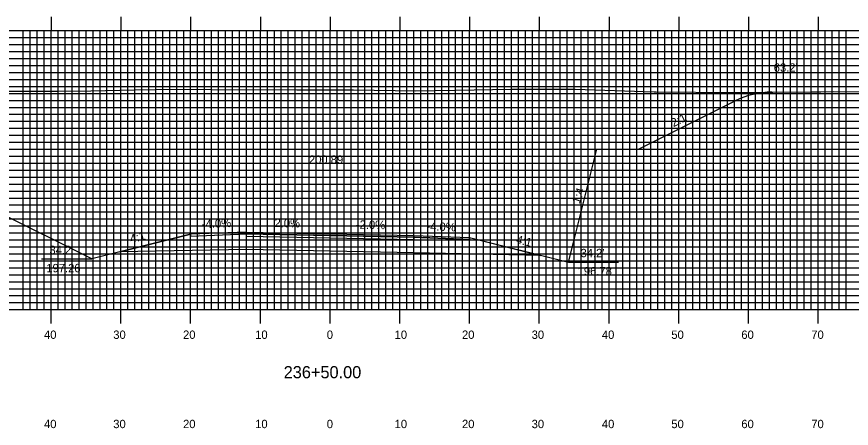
# Model space of a CAD drawing. Extents: x 1800749 to 1801092, y 442591 to 442811.
# Drawn here: x 1800869.6 to 1800989.3, y 442651.6 to 442710.7 of the extents above; entities that cross this region are included whole.
import ezdxf

# ---------------------------------------------------------------- set-up
doc = ezdxf.new("R2010")
doc.units = 0
for name, color, linetype in [('ANNOTATION', 7, 'Continuous'), ('D_Roadway_Centerline', 7, 'Continuous'), ('D_Roadway_Centerline_Text', 7, 'Continuous'), ('D_Roadway_Edge_Shoulder', 7, 'Continuous'), ('D_Roadway_Edge_TW', 7, 'Continuous'), ('D_Roadway_Pavement', 7, 'Continuous'), ('D_Roadway_SlopeLines', 7, 'Continuous'), ('D_Roadway_SubGrade', 7, 'Continuous'), ('D_Text_Standard', 7, 'Continuous'), ('H_V ANNOTATION', 7, 'Continuous'), ('MAJOR', 7, 'Continuous'), ('MINOR', 7, 'Continuous'), ('PDRAIN', 7, 'Continuous'), ('S_Roadway_Centerline', 7, 'Continuous')]:
    doc.layers.add(name, color=color, linetype=linetype)

msp = doc.modelspace()

# ---------------------------------------------------------------- linework, layer by layer
at = {"layer": 'ANNOTATION'}
for p, q in [((1800960.78, 442692.67), (1800972.63, 442698.59)), ((1800958.78, 442691.67), (1800960.78, 442692.67)), ((1800949.72, 442679.45), (1800952.78, 442691.67)), ((1800952.78, 442691.67), (1800958.78, 442691.67)), ((1800948.72, 442675.45), (1800949.72, 442679.45))]:
    msp.add_line(p, q, dxfattribs=at)
msp.add_arc((1800978, 442687.86), 12, 90.3864, 116.5651, dxfattribs=at)
at = {"layer": 'D_Roadway_Edge_Shoulder'}
for points in [[(1800902.55, 442679.79), (1800894.55, 442679.47), (1800894.55, 442679.22), (1800902.55, 442679.54)], [(1800926.55, 442679.31), (1800934.55, 442678.99), (1800934.55, 442678.74), (1800926.55, 442679.06)]]:
    msp.add_lwpolyline(points, close=True, dxfattribs=at)
at = {"layer": 'D_Roadway_Edge_TW'}
msp.add_lwpolyline([(1800902.55, 442679.54), (1800902.55, 442679.79), (1800914.55, 442679.55), (1800926.55, 442679.31), (1800926.55, 442679.06), (1800914.55, 442679.3)], close=True, dxfattribs=at)
at = {"layer": 'D_Roadway_Pavement'}
msp.add_lwpolyline([(1800902.55, 442679.13), (1800902.55, 442679.54), (1800914.55, 442679.3), (1800926.55, 442679.06), (1800926.55, 442678.65), (1800914.55, 442678.89)], close=True, dxfattribs=at)
at = {"layer": 'D_Roadway_SlopeLines'}
msp.add_line((1800880.38, 442675.93), (1800837.81, 442697.21), dxfattribs=at)
for points in [[(1800894.55, 442679.47), (1800880.38, 442675.93)], [(1800934.55, 442678.99), (1800948.72, 442675.45)]]:
    msp.add_lwpolyline(points, dxfattribs=at)
at = {"layer": 'D_Roadway_SubGrade'}
msp.add_lwpolyline([(1800902.55, 442677.29), (1800884.38, 442676.93), (1800894.55, 442679.47), (1800894.55, 442679.22), (1800902.55, 442679.54), (1800914.55, 442679.3), (1800926.55, 442679.06), (1800934.55, 442678.74), (1800934.55, 442678.99), (1800944.72, 442676.45), (1800926.55, 442676.81), (1800914.55, 442677.05)], close=True, dxfattribs=at)
at = {"layer": 'MAJOR'}
for p, q in [((1800874.55, 442710.67), (1800874.55, 442708.67)), ((1800884.55, 442710.67), (1800884.55, 442708.67)), ((1800894.55, 442710.67), (1800894.55, 442708.67)), ((1800904.55, 442710.67), (1800904.55, 442708.67)), ((1800914.55, 442710.67), (1800914.55, 442708.67)), ((1800924.55, 442710.67), (1800924.55, 442708.67)), ((1800934.55, 442710.67), (1800934.55, 442708.67)), ((1800944.55, 442710.67), (1800944.55, 442708.67)), ((1800954.55, 442710.67), (1800954.55, 442708.67)), ((1800964.55, 442710.67), (1800964.55, 442708.67)), ((1800974.55, 442710.67), (1800974.55, 442708.67)), ((1800984.55, 442710.67), (1800984.55, 442708.67)), ((1800774.55, 442708.67), (1801054.55, 442708.67)), ((1800774.55, 442708.67), (1801054.55, 442708.67)), ((1800874.55, 442668.67), (1800874.55, 442708.67)), ((1800884.55, 442668.67), (1800884.55, 442708.67)), ((1800894.55, 442668.67), (1800894.55, 442708.67)), ((1800904.55, 442668.67), (1800904.55, 442708.67)), ((1800914.55, 442668.67), (1800914.55, 442708.67)), ((1800924.55, 442668.67), (1800924.55, 442708.67)), ((1800934.55, 442668.67), (1800934.55, 442708.67)), ((1800944.55, 442668.67), (1800944.55, 442708.67)), ((1800954.55, 442668.67), (1800954.55, 442708.67)), ((1800964.55, 442668.67), (1800964.55, 442708.67)), ((1800974.55, 442668.67), (1800974.55, 442708.67)), ((1800984.55, 442668.67), (1800984.55, 442708.67)), ((1800774.55, 442703.67), (1801054.55, 442703.67)), ((1800774.55, 442698.67), (1801054.55, 442698.67)), ((1800774.55, 442693.67), (1801054.55, 442693.67)), ((1800774.55, 442688.67), (1801054.55, 442688.67)), ((1800774.55, 442683.67), (1801054.55, 442683.67)), ((1800774.55, 442678.67), (1801054.55, 442678.67)), ((1800774.55, 442673.67), (1801054.55, 442673.67)), ((1800774.55, 442668.67), (1801054.55, 442668.67)), ((1800774.55, 442668.67), (1801054.55, 442668.67)), ((1800874.55, 442666.66), (1800874.55, 442668.67)), ((1800884.55, 442666.66), (1800884.55, 442668.67)), ((1800894.55, 442666.66), (1800894.55, 442668.67)), ((1800904.55, 442666.66), (1800904.55, 442668.67)), ((1800914.55, 442666.66), (1800914.55, 442668.67)), ((1800924.55, 442666.66), (1800924.55, 442668.67)), ((1800934.55, 442666.66), (1800934.55, 442668.67)), ((1800944.55, 442666.66), (1800944.55, 442668.67)), ((1800954.55, 442666.66), (1800954.55, 442668.67)), ((1800964.55, 442666.66), (1800964.55, 442668.67)), ((1800974.55, 442666.66), (1800974.55, 442668.67)), ((1800984.55, 442666.66), (1800984.55, 442668.67))]:
    msp.add_line(p, q, dxfattribs=at)
at = {"layer": 'MINOR'}
for p, q in [((1800870.55, 442668.67), (1800870.55, 442708.67)), ((1800871.55, 442668.67), (1800871.55, 442708.67)), ((1800872.55, 442668.67), (1800872.55, 442708.67)), ((1800873.55, 442668.67), (1800873.55, 442708.67)), ((1800875.55, 442668.67), (1800875.55, 442708.67)), ((1800876.55, 442668.67), (1800876.55, 442708.67)), ((1800877.55, 442668.67), (1800877.55, 442708.67)), ((1800878.55, 442668.67), (1800878.55, 442708.67)), ((1800879.55, 442668.67), (1800879.55, 442708.67)), ((1800880.55, 442668.67), (1800880.55, 442708.67)), ((1800881.55, 442668.67), (1800881.55, 442708.67)), ((1800882.55, 442668.67), (1800882.55, 442708.67)), ((1800883.55, 442668.67), (1800883.55, 442708.67)), ((1800885.55, 442668.67), (1800885.55, 442708.67)), ((1800886.55, 442668.67), (1800886.55, 442708.67)), ((1800887.55, 442668.67), (1800887.55, 442708.67)), ((1800888.55, 442668.67), (1800888.55, 442708.67)), ((1800889.55, 442668.67), (1800889.55, 442708.67)), ((1800890.55, 442668.67), (1800890.55, 442708.67)), ((1800891.55, 442668.67), (1800891.55, 442708.67)), ((1800892.55, 442668.67), (1800892.55, 442708.67)), ((1800893.55, 442668.67), (1800893.55, 442708.67)), ((1800895.55, 442668.67), (1800895.55, 442708.67)), ((1800896.55, 442668.67), (1800896.55, 442708.67)), ((1800897.55, 442668.67), (1800897.55, 442708.67)), ((1800898.55, 442668.67), (1800898.55, 442708.67)), ((1800899.55, 442668.67), (1800899.55, 442708.67)), ((1800900.55, 442668.67), (1800900.55, 442708.67)), ((1800901.55, 442668.67), (1800901.55, 442708.67)), ((1800902.55, 442668.67), (1800902.55, 442708.67)), ((1800903.55, 442668.67), (1800903.55, 442708.67)), ((1800905.55, 442668.67), (1800905.55, 442708.67)), ((1800906.55, 442668.67), (1800906.55, 442708.67)), ((1800907.55, 442668.67), (1800907.55, 442708.67)), ((1800908.55, 442668.67), (1800908.55, 442708.67)), ((1800909.55, 442668.67), (1800909.55, 442708.67)), ((1800910.55, 442668.67), (1800910.55, 442708.67)), ((1800911.55, 442668.67), (1800911.55, 442708.67)), ((1800912.55, 442668.67), (1800912.55, 442708.67)), ((1800913.55, 442668.67), (1800913.55, 442708.67)), ((1800915.55, 442668.67), (1800915.55, 442708.67)), ((1800916.55, 442668.67), (1800916.55, 442708.67)), ((1800917.55, 442668.67), (1800917.55, 442708.67)), ((1800918.55, 442668.67), (1800918.55, 442708.67)), ((1800919.55, 442668.67), (1800919.55, 442708.67)), ((1800920.55, 442668.67), (1800920.55, 442708.67)), ((1800921.55, 442668.67), (1800921.55, 442708.67)), ((1800922.55, 442668.67), (1800922.55, 442708.67)), ((1800923.55, 442668.67), (1800923.55, 442708.67)), ((1800925.55, 442668.67), (1800925.55, 442708.67)), ((1800926.55, 442668.67), (1800926.55, 442708.67)), ((1800927.55, 442668.67), (1800927.55, 442708.67)), ((1800928.55, 442668.67), (1800928.55, 442708.67)), ((1800929.55, 442668.67), (1800929.55, 442708.67)), ((1800930.55, 442668.67), (1800930.55, 442708.67)), ((1800931.55, 442668.67), (1800931.55, 442708.67)), ((1800932.55, 442668.67), (1800932.55, 442708.67)), ((1800933.55, 442668.67), (1800933.55, 442708.67)), ((1800935.55, 442668.67), (1800935.55, 442708.67)), ((1800936.55, 442668.67), (1800936.55, 442708.67)), ((1800937.55, 442668.67), (1800937.55, 442708.67)), ((1800938.55, 442668.67), (1800938.55, 442708.67)), ((1800939.55, 442668.67), (1800939.55, 442708.67)), ((1800940.55, 442668.67), (1800940.55, 442708.67)), ((1800941.55, 442668.67), (1800941.55, 442708.67)), ((1800942.55, 442668.67), (1800942.55, 442708.67)), ((1800943.55, 442668.67), (1800943.55, 442708.67)), ((1800945.55, 442668.67), (1800945.55, 442708.67)), ((1800946.55, 442668.67), (1800946.55, 442708.67)), ((1800947.55, 442668.67), (1800947.55, 442708.67)), ((1800948.55, 442668.67), (1800948.55, 442708.67)), ((1800949.55, 442668.67), (1800949.55, 442708.67)), ((1800950.55, 442668.67), (1800950.55, 442708.67)), ((1800951.55, 442668.67), (1800951.55, 442708.67)), ((1800952.55, 442668.67), (1800952.55, 442708.67)), ((1800953.55, 442668.67), (1800953.55, 442708.67)), ((1800955.55, 442668.67), (1800955.55, 442708.67)), ((1800956.55, 442668.67), (1800956.55, 442708.67)), ((1800957.55, 442668.67), (1800957.55, 442708.67)), ((1800958.55, 442668.67), (1800958.55, 442708.67)), ((1800959.55, 442668.67), (1800959.55, 442708.67)), ((1800960.55, 442668.67), (1800960.55, 442708.67)), ((1800961.55, 442668.67), (1800961.55, 442708.67)), ((1800962.55, 442668.67), (1800962.55, 442708.67)), ((1800963.55, 442668.67), (1800963.55, 442708.67)), ((1800965.55, 442668.67), (1800965.55, 442708.67)), ((1800966.55, 442668.67), (1800966.55, 442708.67)), ((1800967.55, 442668.67), (1800967.55, 442708.67)), ((1800968.55, 442668.67), (1800968.55, 442708.67)), ((1800969.55, 442668.67), (1800969.55, 442708.67)), ((1800970.55, 442668.67), (1800970.55, 442708.67)), ((1800971.55, 442668.67), (1800971.55, 442708.67)), ((1800972.55, 442668.67), (1800972.55, 442708.67)), ((1800973.55, 442668.67), (1800973.55, 442708.67)), ((1800975.55, 442668.67), (1800975.55, 442708.67)), ((1800976.55, 442668.67), (1800976.55, 442708.67)), ((1800977.55, 442668.67), (1800977.55, 442708.67)), ((1800978.55, 442668.67), (1800978.55, 442708.67)), ((1800979.55, 442668.67), (1800979.55, 442708.67)), ((1800980.55, 442668.67), (1800980.55, 442708.67)), ((1800981.55, 442668.67), (1800981.55, 442708.67)), ((1800982.55, 442668.67), (1800982.55, 442708.67)), ((1800983.55, 442668.67), (1800983.55, 442708.67)), ((1800985.55, 442668.67), (1800985.55, 442708.67)), ((1800986.55, 442668.67), (1800986.55, 442708.67)), ((1800987.55, 442668.67), (1800987.55, 442708.67)), ((1800988.55, 442668.67), (1800988.55, 442708.67)), ((1800774.55, 442707.67), (1801054.55, 442707.67)), ((1800774.55, 442706.67), (1801054.55, 442706.67)), ((1800774.55, 442705.67), (1801054.55, 442705.67)), ((1800774.55, 442704.67), (1801054.55, 442704.67)), ((1800774.55, 442702.67), (1801054.55, 442702.67)), ((1800774.55, 442701.67), (1801054.55, 442701.67)), ((1800774.55, 442700.67), (1801054.55, 442700.67)), ((1800774.55, 442699.67), (1801054.55, 442699.67)), ((1800774.55, 442697.67), (1801054.55, 442697.67)), ((1800774.55, 442696.67), (1801054.55, 442696.67)), ((1800774.55, 442695.67), (1801054.55, 442695.67)), ((1800774.55, 442694.67), (1801054.55, 442694.67)), ((1800774.55, 442692.67), (1801054.55, 442692.67)), ((1800774.55, 442691.67), (1801054.55, 442691.67)), ((1800774.55, 442690.67), (1801054.55, 442690.67)), ((1800774.55, 442689.67), (1801054.55, 442689.67)), ((1800774.55, 442687.67), (1801054.55, 442687.67)), ((1800774.55, 442686.67), (1801054.55, 442686.67)), ((1800774.55, 442685.67), (1801054.55, 442685.67)), ((1800774.55, 442684.67), (1801054.55, 442684.67)), ((1800774.55, 442682.67), (1801054.55, 442682.67)), ((1800774.55, 442681.67), (1801054.55, 442681.67)), ((1800774.55, 442680.67), (1801054.55, 442680.67)), ((1800774.55, 442679.67), (1801054.55, 442679.67)), ((1800774.55, 442677.67), (1801054.55, 442677.67)), ((1800774.55, 442676.67), (1801054.55, 442676.67)), ((1800774.55, 442675.67), (1801054.55, 442675.67)), ((1800774.55, 442674.67), (1801054.55, 442674.67)), ((1800774.55, 442672.67), (1801054.55, 442672.67)), ((1800774.55, 442671.67), (1801054.55, 442671.67)), ((1800774.55, 442670.67), (1801054.55, 442670.67)), ((1800774.55, 442669.67), (1801054.55, 442669.67))]:
    msp.add_line(p, q, dxfattribs=at)
at = {"layer": 'PDRAIN'}
for p, q in [((1800873.14, 442675.93), (1800880.38, 442675.93)), ((1800948.72, 442675.45), (1800955.92, 442675.45))]:
    msp.add_line(p, q, dxfattribs=at)
at = {"layer": 'S_Roadway_Centerline'}
msp.add_lwpolyline([(1800868.46, 442699.98), (1800875.56, 442700.01), (1800880.24, 442700.05), (1800886.51, 442700.18), (1800892.55, 442700.29), (1800897.6, 442700.22), (1800909.76, 442700.2), (1800917.91, 442700.17), (1800926.85, 442700.03), (1800935.21, 442700.19), (1800940.45, 442700.28), (1800949.71, 442700.27), (1800961.01, 442699.89), (1800961.31, 442699.89), (1800972.64, 442699.82), (1800983.45, 442699.9), (1800984.93, 442699.88), (1800986.67, 442699.95), (1801005.14, 442699.75)], dxfattribs=at)

# ---------------------------------------------------------------- texts
at = {"layer": 'ANNOTATION'}
for s, rotation, p in [('2:1', 26.5651, (1800963.8, 442694.82)), ('1:4', 70.516, (1800950.32, 442683.76)), ('-4.0%', 2.2906, (1800896.18, 442680.34)), ('2.0%', 358.8542, (1800906.56, 442680.51)), ('-2.0%', 358.8542, (1800918.24, 442680.28)), ('-4.0%', 357.7094, (1800928.34, 442680.04)), ('4:1', 14.0362, (1800886, 442678.2)), ('4:1', 345.9638, (1800941.14, 442678.21))]:
    msp.add_text(s, height=1.2, rotation=rotation, dxfattribs=at).set_placement(p)
for s, p in [("34.2'", (1800874.3, 442676.62)), ("34.2'", (1800950.46, 442676.18)), ('197.26', (1800873.85, 442674.02)), ('196.78', (1800950.05, 442673.58))]:
    msp.add_text(s, height=1.2, dxfattribs=at).set_placement(p)
at = {"layer": 'D_Roadway_Centerline'}
for s, p in [('C', (1800914.54, 442679.55)), ('L', (1800914.55, 442679.55))]:
    msp.add_text(s, height=0.0146, dxfattribs=at).set_placement(p)
at = {"layer": 'D_Roadway_Centerline_Text'}
msp.add_text('200.89', height=1.2, dxfattribs=at).set_placement((1800911.51, 442689.58))
at = {"layer": 'D_Text_Standard'}
msp.add_text("63.2'", height=1.2, dxfattribs=at).set_placement((1800978.17, 442702.78))
at = {"layer": 'H_V ANNOTATION'}
for s, height, p in [('40', 1.2, (1800873.52, 442664.47)), ('30', 1.2, (1800883.45, 442664.47)), ('20', 1.2, (1800893.46, 442664.47)), ('10', 1.2, (1800903.8, 442664.47)), ('0', 1.2, (1800914.07, 442664.47)), ('10', 1.2, (1800923.8, 442664.47)), ('20', 1.2, (1800933.46, 442664.47)), ('30', 1.2, (1800943.45, 442664.47)), ('40', 1.2, (1800953.52, 442664.47)), ('50', 1.2, (1800963.48, 442664.47)), ('60', 1.2, (1800973.52, 442664.47)), ('70', 1.2, (1800983.55, 442664.47)), ('236+50.00', 1.75, (1800907.89, 442658.82)), ('40', 1.2, (1800873.52, 442651.67)), ('30', 1.2, (1800883.45, 442651.67)), ('20', 1.2, (1800893.46, 442651.67)), ('10', 1.2, (1800903.8, 442651.67)), ('0', 1.2, (1800914.07, 442651.67)), ('10', 1.2, (1800923.8, 442651.67)), ('20', 1.2, (1800933.46, 442651.67)), ('30', 1.2, (1800943.45, 442651.67)), ('40', 1.2, (1800953.52, 442651.67)), ('50', 1.2, (1800963.48, 442651.67)), ('60', 1.2, (1800973.52, 442651.67)), ('70', 1.2, (1800983.55, 442651.67))]:
    msp.add_text(s, height=height, dxfattribs=at).set_placement(p)

doc.saveas('drawing.dxf')
